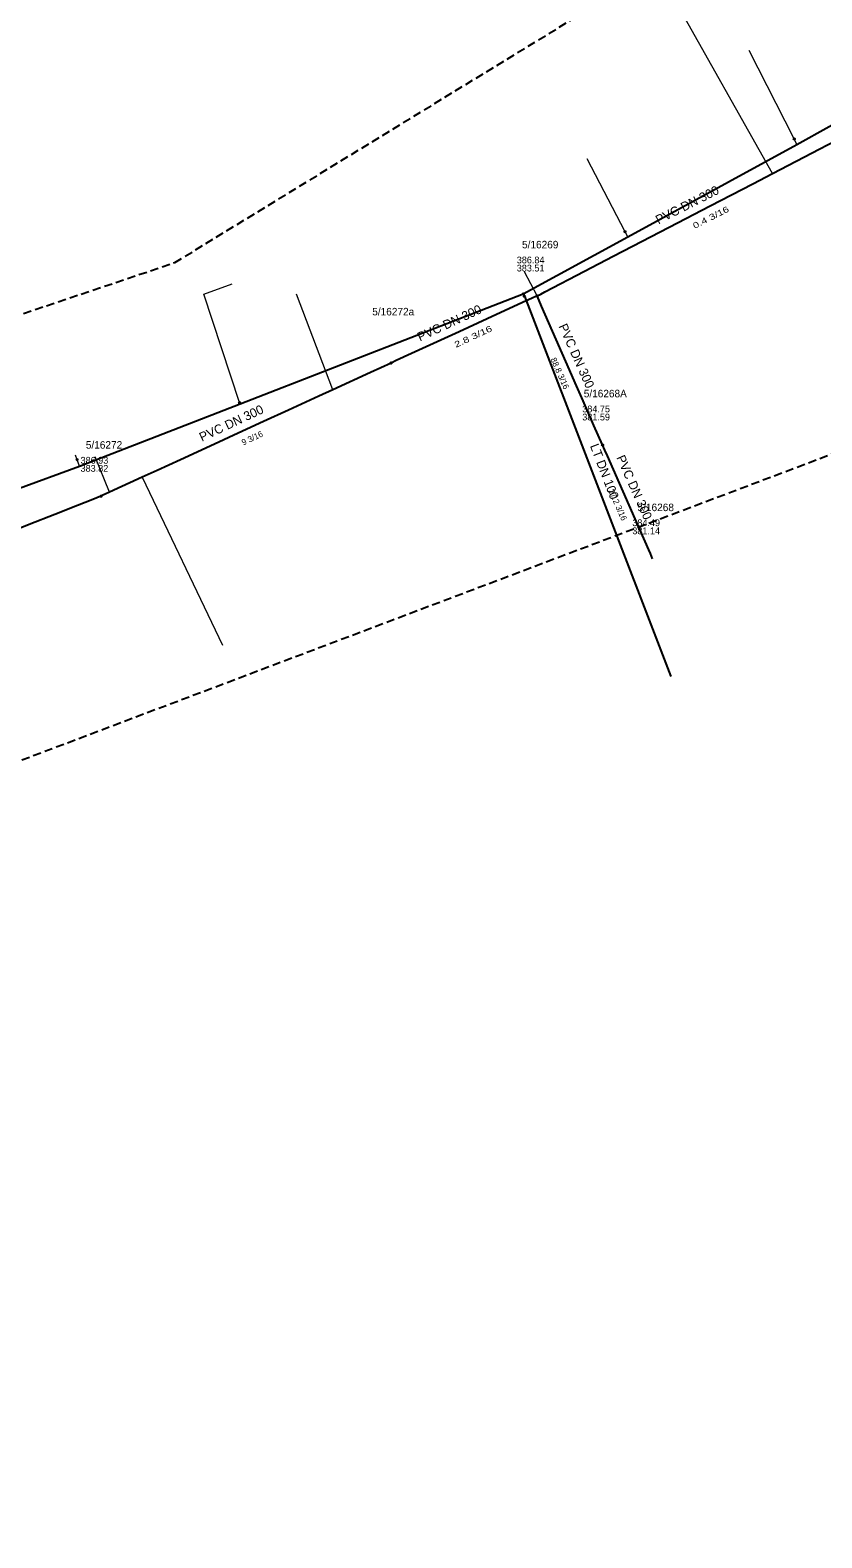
# Model space of a CAD drawing. Extents: x -772855 to -772151, y -1033136 to -1032581.
# Drawn here: x -772481.3 to -772376, y -1033111.6 to -1032911.1 of the extents above; entities that cross this region are included whole.
import ezdxf

# ---------------------------------------------------------------- set-up
doc = ezdxf.new("R2010")
doc.units = 0
doc.header["$LTSCALE"] = 0.36
doc.header["$PDMODE"] = 32
doc.header["$PDSIZE"] = 0.18
doc.linetypes.add('MEDIUM_DASHED', pattern=[4.5, 3, -1.5])
for name, color, linetype in [('15', 7, 'Continuous'), ('17', 7, 'Continuous'), ('3', 7, 'Continuous'), ('4', 7, 'Continuous'), ('5', 7, 'Continuous'), ('56', 7, 'Continuous')]:
    doc.layers.add(name, color=color, linetype=linetype)
for name, color, linetype, lineweight in [('16', 7, 'Continuous', 25), ('2', 7, 'Continuous', 25), ('57', 7, 'Continuous', 13), ('58', 7, 'Continuous', 13), ('62', 7, 'MEDIUM_DASHED', 25)]:
    doc.layers.add(name, color=color, linetype=linetype, lineweight=lineweight)

msp = doc.modelspace()

# ---------------------------------------------------------------- linework, layer by layer
at = {"layer": '15'}
for p in [(-772379.714, -1032925.574), (-772402.21, -1032937.913), (-772415.74, -1032946.165), (-772415.582, -1032946.491), (-772453.439, -1032960.623), (-772475.04, -1032968.218)]:
    msp.add_point(p, dxfattribs=at)
at = {"layer": '16'}
for p, q in [((-772415.739, -1032946.164), (-772415.581, -1032946.491)), ((-772415.581, -1032946.491), (-772396.136, -1032997.046))]:
    msp.add_line(p, q, dxfattribs=at)
for points in [[(-772415.739, -1032946.164), (-772401.855, -1032938.587), (-772379.355, -1032926.307), (-772357.856, -1032914.338), (-772338.431, -1032900.962), (-772336.468, -1032899.579), (-772334.822, -1032898.421), (-772320.116, -1032888.065), (-772308.796, -1032878.817), (-772295.074, -1032865.513), (-772294.263, -1032864.445)], [(-772601.451, -1033015.905), (-772591.094, -1033012.087), (-772576.384, -1033006.664), (-772575.686, -1033006.407), (-772533.557, -1032990.768), (-772513.381, -1032983.278), (-772504.351, -1032979.926), (-772500.166, -1032978.372), (-772474.732, -1032969.061), (-772453.383, -1032960.774), (-772415.739, -1032946.164)]]:
    msp.add_lwpolyline(points, dxfattribs=at)
at = {"layer": '2'}
for points in [[(-772413.9, -1032946.45), (-772413.42, -1032946.2), (-772412.857, -1032945.907), (-772407.577, -1032943.16), (-772403.768, -1032941.178), (-772399.916, -1032939.173), (-772395.222, -1032936.731), (-772390.907, -1032934.486), (-772385.235, -1032931.535), (-772382.615, -1032930.172), (-772376.302, -1032926.887), (-772374.27, -1032925.83), (-772371.818, -1032924.554), (-772370.95, -1032924.102), (-772370.586, -1032923.913), (-772370.08, -1032923.65)], [(-772413.9, -1032946.45), (-772414.646, -1032946.792), (-772415.345, -1032947.113), (-772419.273, -1032948.917), (-772424.271, -1032951.212), (-772430.58, -1032954.11), (-772432.633, -1032955.052), (-772433.314, -1032955.365)], [(-772405.193, -1032966.254), (-772405.766, -1032964.951), (-772406.336, -1032963.654), (-772407.77, -1032960.392), (-772408.646, -1032958.399), (-772410.075, -1032955.151), (-772411.834, -1032951.148), (-772413.295, -1032947.824), (-772413.633, -1032947.056), (-772413.9, -1032946.45)], [(-772433.314, -1032955.365), (-772436.025, -1032956.61), (-772441.048, -1032958.916), (-772442.895, -1032959.765), (-772446.947, -1032961.625), (-772450.275, -1032963.154), (-772453.623, -1032964.691), (-772456.799, -1032966.15), (-772461.314, -1032968.223), (-772464.397, -1032969.639), (-772466.388, -1032970.553), (-772470.747, -1032972.555), (-772471.322, -1032972.819), (-772471.622, -1032972.957), (-772471.89, -1032973.08)], [(-772398.54, -1032981.39), (-772398.837, -1032980.713), (-772399.063, -1032980.199), (-772400.877, -1032976.088), (-772404.559, -1032967.697), (-772404.876, -1032966.975), (-772405.193, -1032966.254)], [(-772471.89, -1032973.08), (-772472.428, -1032973.292), (-772472.961, -1032973.503), (-772474.98, -1032974.302), (-772477.998, -1032975.495), (-772481.402, -1032976.842), (-772485.412, -1032978.428), (-772488.512, -1032979.653), (-772491.616, -1032980.881), (-772492.384, -1032981.185), (-772495.816, -1032982.542), (-772499.052, -1032983.822), (-772501.537, -1032984.805), (-772502.334, -1032985.12), (-772502.89, -1032985.34)]]:
    msp.add_lwpolyline(points, dxfattribs=at)
at = {"layer": '4'}
for p in [(-772413.9, -1032946.45), (-772433.314, -1032955.365), (-772405.193, -1032966.254), (-772471.89, -1032973.08)]:
    msp.add_point(p, dxfattribs=at)
at = {"layer": '57'}
for p, q in [((-772382.615, -1032930.172), (-772395.58, -1032907.11)), ((-772413.9, -1032946.45), (-772415.56, -1032943.26)), ((-772441.048, -1032958.916), (-772445.88, -1032946.21)), ((-772470.747, -1032972.555), (-772472.64, -1032967.84)), ((-772466.388, -1032970.553), (-772455.7, -1032992.9))]:
    msp.add_line(p, q, dxfattribs=at)
at = {"layer": '58'}
for points in [[(-772379.355, -1032926.307), (-772379.714, -1032925.574), (-772385.72, -1032913.82)], [(-772401.855, -1032938.587), (-772402.21, -1032937.913), (-772407.26, -1032928.24)], [(-772453.383, -1032960.775), (-772453.439, -1032960.623), (-772458.2, -1032946.2), (-772454.44, -1032944.83)], [(-772474.732, -1032969.061), (-772475.04, -1032968.218), (-772475.265, -1032967.63)]]:
    msp.add_lwpolyline(points, dxfattribs=at)
at = {"layer": '62'}
msp.add_lwpolyline([(-772807.858, -1033073.22), (-772807.858, -1033073.204), (-772761.644, -1033042.737), (-772462.077, -1032942.017), (-772241.248, -1032806.814), (-772216.072, -1032836.7), (-772367.717, -1032964.854), (-772756.015, -1033111.568)], close=True, dxfattribs=at)

# ---------------------------------------------------------------- texts
at = {"layer": '17'}
msp.add_text('LT DN 100 ', height=1.2, rotation=291, dxfattribs=at).set_placement((-772406.889, -1032966.378))
at = {"layer": '3'}
for s, height, rotation, p in [('PVC DN 300', 1.2, 27, (-772397.761, -1032936.955)), ('PVC DN 300', 1.2, 25, (-772429.466, -1032952.527)), ('PVC DN 300', 1.2, 294, (-772411.071, -1032950.466)), ('88.8 3/16', 0.8, 294, (-772412.139, -1032954.868)), ('PVC DN 300', 1.2, 25, (-772458.46, -1032965.842)), ('9 3/16 ', 0.8, 25, (-772452.95, -1032966.337)), ('PVC DN 300', 1.2, 294, (-772403.392, -1032967.936)), ('27.2 3/16', 0.8, 294, (-772404.459, -1032972.337))]:
    msp.add_text(s, height=height, rotation=rotation, dxfattribs=at).set_placement(p)
for s, rotation, width, p in [('0.4 3/16 ', 27, 1.35, (-772392.943, -1032937.546)), ('2.8 3/16 ', 25, 1.4, (-772424.682, -1032953.355))]:
    msp.add_text(s, height=0.8, rotation=rotation, dxfattribs=dict(at, width=width)).set_placement(p)
at = {"layer": '5'}
for s, p in [('5/16269', (-772415.9, -1032940.121)), ('5/16272a ', (-772435.813, -1032949.036)), ('5/16268A ', (-772407.693, -1032959.926)), ('5/16272', (-772473.89, -1032966.751)), ('5/16268', (-772400.54, -1032975.061))]:
    msp.add_text(s, height=1, dxfattribs=at).set_placement(p)
at = {"layer": '56'}
for s, p in [('386.84', (-772416.598, -1032942.117)), ('383.51', (-772416.598, -1032943.194)), ('384.75', (-772407.892, -1032961.922)), ('381.59', (-772407.892, -1032962.999)), ('386.93', (-772474.588, -1032968.747)), ('383.82', (-772474.588, -1032969.824)), ('384.49', (-772401.238, -1032977.057)), ('381.14', (-772401.238, -1032978.134))]:
    msp.add_text(s, height=0.9, dxfattribs=at).set_placement(p)

doc.saveas('drawing.dxf')
